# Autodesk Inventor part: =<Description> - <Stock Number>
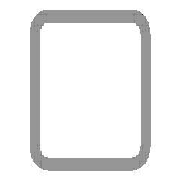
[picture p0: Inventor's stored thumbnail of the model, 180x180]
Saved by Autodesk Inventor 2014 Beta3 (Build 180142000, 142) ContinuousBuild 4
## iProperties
IsCustomPart: 1
_CCFamilyMember: 9
_CCFamilyDisplayName: ANSI AISC (Square) - Tube
_FrameMemberDoc: Frame Member File
_Version: 15.0.0
_GetPNFromCC: 1
Created: 2011-01
Part Number: =<Description> - <Stock Number>
Material: Steel, Mild
Description: Tube
Document SubType Name: Modeling
Standard: ANSI
Designer: Beta-8540w
Standards Organization: ANSI
Language: en-US
Size Designation: 3x3x3/16
Categories: <MemberInstance><Categories><Category DisplayName="Structural Shapes" InternalName="089c4875-fa83-4c05-b084-43b9cc11f5ed" Mnemonic="GRDR"><CategoryParameter Dis
Stock Number: 3x3x3/16
Density: 7.86 g/cm^3
Appearance: Steel
G_L: 28.000 in
G_W: 3.000 in
G_H: 3.000 in
Author: Beta-8540w
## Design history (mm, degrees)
node "Start plane"
node "End plane"
sketch "Sketch"
  geometry: L1 (-38.1, -28.575)-(-38.1, 28.575); L2 (-28.575, 38.1)-(28.575, 38.1); L3 (38.1, 28.575)-(38.1, -28.575); L4 (28.575, -38.1)-(-28.575, -38.1); L5 (-28.575, 33.337)-(28.575, 33.338); L6 (33.338, 28.575)-(33.338, -28.575); L7 (28.575, -33.337)-(-28.575, -33.338); L8 (-33.338, -28.575)-(-33.338, 28.575); L9 (0, 56.102)-(0, -56.102) reference; L10 (-56.102, 0)-(56.102, 0) reference; A1 r 9.525 centre (-28.575, -28.575) between (-38.1, -28.575) and (-28.575, -38.1); A2 r 9.525 centre (-28.575, 28.575) between (-28.575, 38.1) and (-38.1, 28.575); A3 r 9.525 centre (28.575, 28.575) between (38.1, 28.575) and (28.575, 38.1); A4 r 9.525 centre (28.575, -28.575) between (28.575, -38.1) and (38.1, -28.575); A5 r 4.763 centre (-28.575, 28.575) between (-28.575, 33.337) and (-33.338, 28.575); A6 r 4.763 centre (28.575, 28.575) between (33.338, 28.575) and (28.575, 33.338); A7 r 4.763 centre (28.575, -28.575) between (28.575, -33.337) and (33.338, -28.575); A8 r 4.763 centre (-28.575, -28.575) between (-33.338, -28.575) and (-28.575, -33.338)
  constraints: 16 end point, 16 point on circle, 8 centre point, 8 tangent, 4 parallel, 3 equal radius, 2 perpendicular, 7 other
  dimensions: "d10" = 76.2 distance between parallel lines of L2 L4 (= G_H); "d11" = 76.2 distance between parallel lines of L1 L3 (= G_W); "d12" = 4.7625 distance between parallel lines of L3 L6 (= G_T); "d15" = 38.1 distance between parallel lines of L2 L10 (= 0.5 x d10); "d16" = 38.1 distance between parallel lines of L9 L3 (= 0.5 x d11); "d17" = 9.525 radius of A1 (= G_IR)
extrude "Body" new body sketch "Sketch" stored distance "d3" = 711.2 (= G_L); taper "d4" = 0 deg
node "Driven Length"
  sketch "Sketch3"
    geometry: L1 (0, 0)-(10, 0) reference
    constraints: 2 end point, 1 horizontal
  workplane "Work Plane3"
  sketch "Sketch4"
    geometry: L1 (-2, 0)-(12, 0) reference; L2 (-2, 711.2)-(12, 711.2) reference
    dimensions: "d19" = 711.2 distance between parallel lines of L1 L2 (derived)
body "Solid1"
other parameters: "G_W" = 76.2 [user parameter; used in 1 equation term], "G_H" = 76.2 [user parameter; used in 1 equation term], "G_T" = 4.7625 [user parameter; used in 1 equation term], "G_IR" = 9.525 [user parameter; used in 1 equation term], "G_L" = 711.2 (= d19) [user parameter; used in 1 equation term], "G_OFFSET_START" = 0 [user parameter; used in 1 equation term], "G_OFFSET_END" = 0 [user parameter; used in 1 equation term], "d13" = 0 (computed from G_OFFSET_START), "d14" = 711.2 (= G_OFFSET_END + B_L), "B_L" = 711.2 [user parameter; used in 1 equation term], "d18" = 90 deg
